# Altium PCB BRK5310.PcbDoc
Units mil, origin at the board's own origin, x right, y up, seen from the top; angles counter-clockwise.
Board outline 4724.41 x 3149.61 mil, 2 copper layers (Top Layer, Bottom Layer), stack 64.8 mil thick; 32 components, 137 nets, 370 pads, 84 vias.
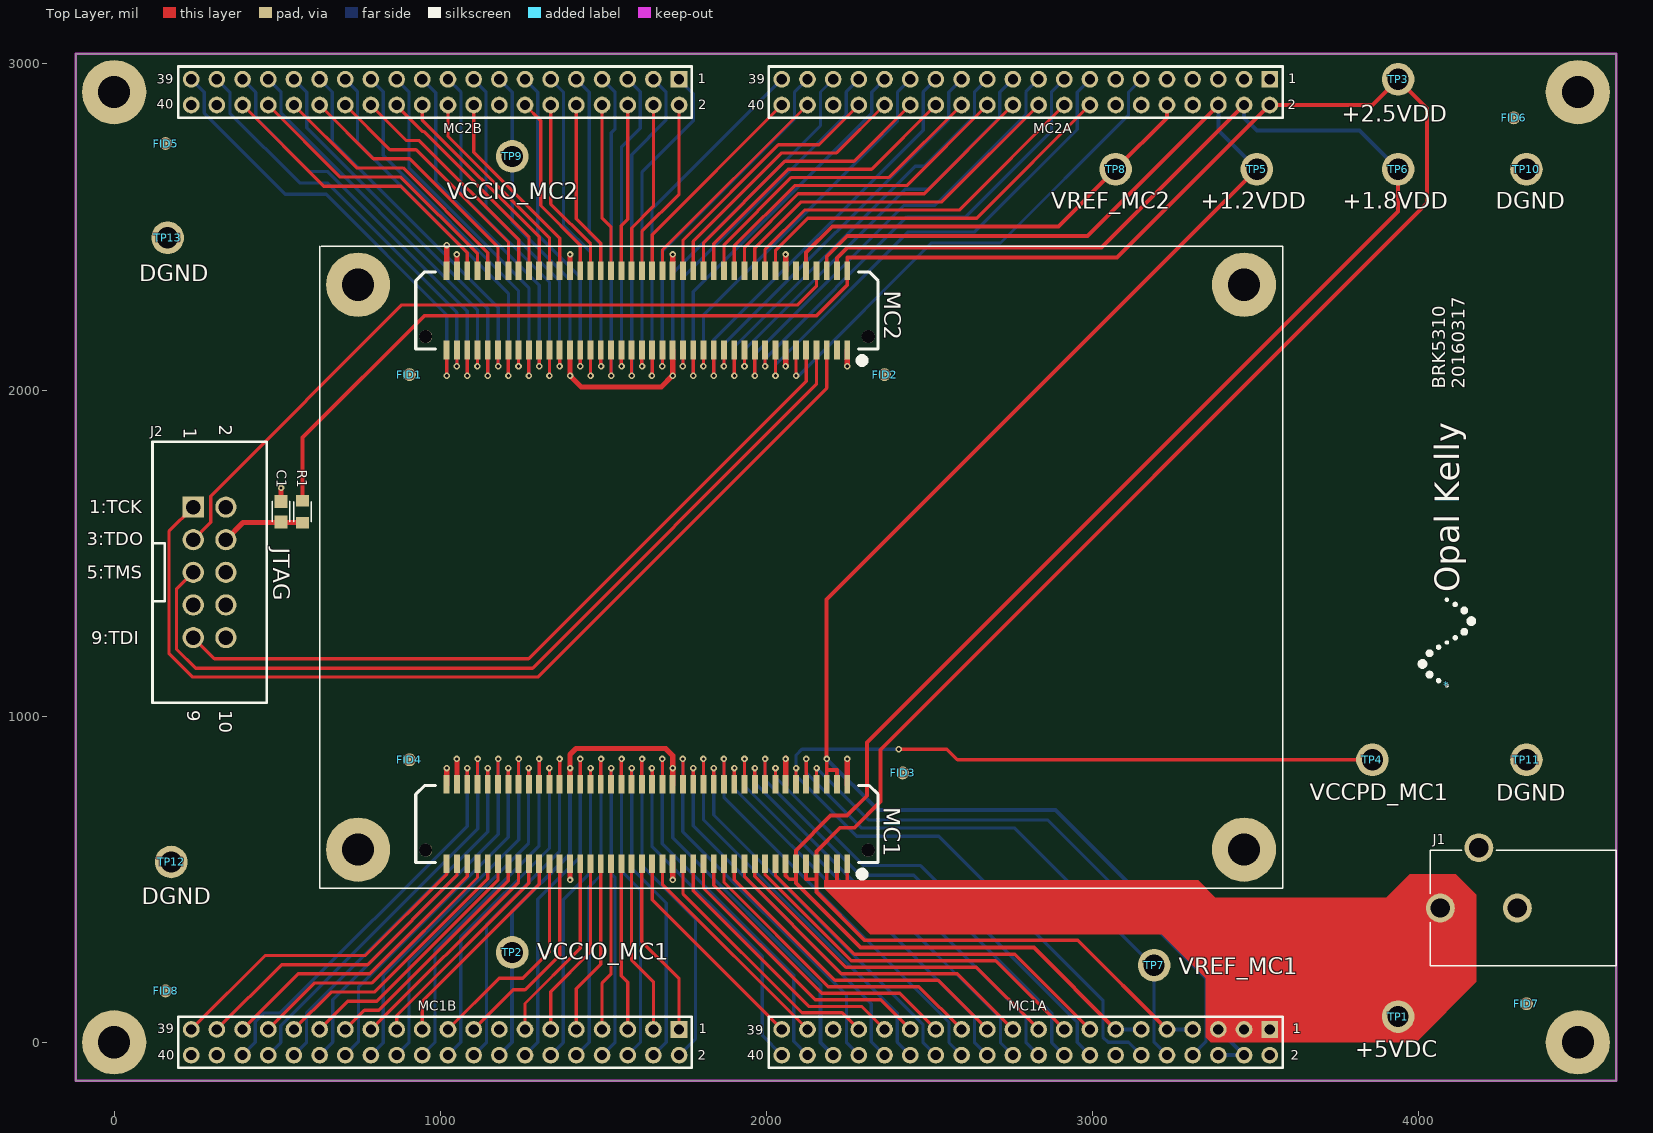
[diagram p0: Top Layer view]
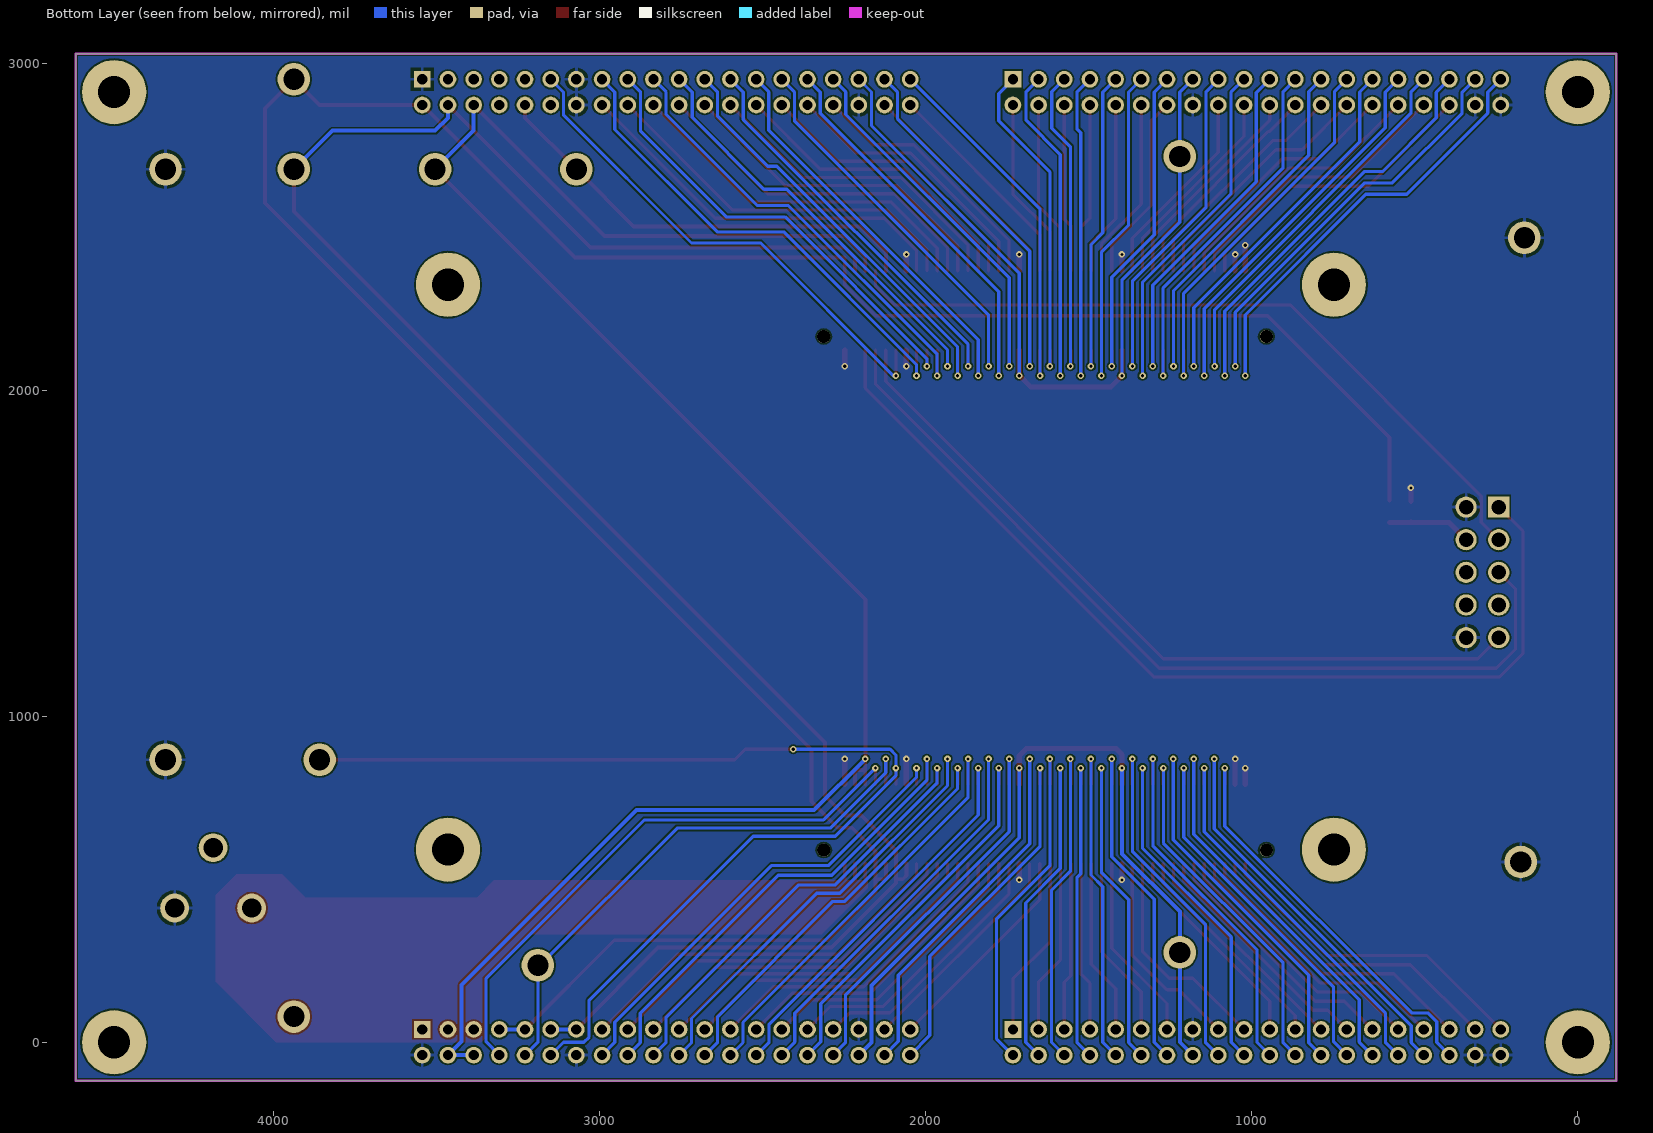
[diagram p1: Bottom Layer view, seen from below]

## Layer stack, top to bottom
Top Solder: solder mask 0.4, Solder Resist, Dk 3.5
Top Layer: signal copper 1.4
Dielectric1: core 62, FR-4, Dk 4.8
Bottom Layer: signal copper 1.4
Bottom Solder: solder mask 0.4, Solder Resist, Dk 3.5

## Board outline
-118.11,-118.11 -118.11,3031.5 4606.3,3031.5 4606.3,-118.11

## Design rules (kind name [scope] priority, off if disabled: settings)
Clearance [All] p1: gap=5
FabricationTestPointUsage TestPointUsage [All] p1: valid=0 allowmultiple=FALSE
FabricationTestpoint Testpoint [All] p1: side=3 testpointundercomponent=TRUE minsize=40 maxsize=100 preferedsize=60 minholesize=0 maxholesize=40 preferedholesize=32 testpointgrid=1 allowsidetop=TRUE allowsidebottom=TRUE usegrid=TRUE gridtolerance=0.01
HoleSize [All] p1: absolutevalues=TRUE maxlimit=236.22 minlimit=10 maxpercent=80.000 minpercent=20.000
MinimumSolderMaskSliver [All] p1: minsoldermaskwidth=3
PolygonConnect "Via Connect" [IsVia] p1: connectstyle=Direct reliefconductorwidth=10 reliefentries=4 polygonreliefangle="90 Angle" airgapwidth=10
PolygonConnect [All] p2: connectstyle=Relief reliefconductorwidth=10 reliefentries=4 polygonreliefangle="90 Angle" airgapwidth=10
RoutingVias [All] p1: holewidth=15 width=25 viastyle="Through Hole" minholewidth=10 minwidth=20 maxholewidth=50 maxwidth=100
SilkToSilkClearance [All] p1: silktosilkclearance=0.1
SilkToSolderMaskClearance SilkscreenOverComponentPads [IsPad] p1: minsilkscreentomaskgap=3 clearancetoexposedcopper=TRUE
SolderMaskExpansion [All] p1: expansion=4
Width okWidthPower [InNetClass('Power')] p1: maxlimit=100 minlimit=10 preferedwidth=10 minimp=50.000000 maximp=50.000000 favimp=50.000000
Width [All] p2: maxlimit=40 minlimit=6 preferedwidth=7 minimp=50.000000 maximp=50.000000 favimp=50.000000
24 further rules are at their usual default settings.

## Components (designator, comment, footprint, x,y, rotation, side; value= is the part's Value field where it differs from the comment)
* "Opal Kelly Logo" okLogo-23x5 4086.61,1094.49 r90 top
C1 "C0603C104K4RACTU" CAPC1608N 511.89,1626.89 r270 top
FID1 "FIDUCIAL" FID1MM/2MM-SS 905.51,2047.24 r90 top
FID2 "FIDUCIAL" FID1MM/2MM-SS 2362.21,2047.24 r90 top
FID3 "FIDUCIAL" FID1MM/2MM-SS 2417.89,825.89 r90 top
FID4 "FIDUCIAL" FID1MM/2MM-SS 905.51,866.14 r90 top
FID5 "FIDUCIAL" FID1MM/2MM-SS 157.48,2755.91 r90 top
FID6 "FIDUCIAL" FID1MM/2MM-SS 4291.34,2834.65 r90 top
FID7 "FIDUCIAL" FID1MM/2MM-SS 4330.71,118.11 r90 top
FID8 "FIDUCIAL" FID1MM/2MM-SS 157.48,157.48 r90 top
J1 "PJ-102AH" CUI-PJ102A 4605.83,411.5 r90 top
J2 "JTAG" HDR2X5-SHRD 292.52,1440.94 r270 top
MC1 "BTE-040-01-F-D-A" BTE-040 1633.86,669.29 r180 top locked
MC1A "0877584016" HDR2X20-2MM 2795.28,0 r180 top locked
MC1B "0877584016" HDR2X20-2MM 984.25,0 r180 top locked
MC2 "BTE-040-01-F-D-A" BTE-040 1633.86,2244.09 r180 top locked
MC2A "0877584016" HDR2X20-2MM 2795.28,2913.39 r180 top locked
MC2B "0877584016" HDR2X20-2MM 984.25,2913.39 r180 top locked
R1 "CRCW06030000Z0EA" RESC1608N 577.89,1626.89 r90 top
TP1 "+5VDC" TP_MED 3937.01,78.74 r0 top
TP2 "VCCIO_MC1" TP_MED 1220.47,275.59 r0 top
TP3 "+2.5VDD" TP_MED 3937.01,2952.76 r0 top
TP4 "VCCPD_MC1" TP_MED 3858.27,866.14 r0 top
TP5 "+1.2VDD" TP_MED 3503.94,2677.17 r0 top
TP6 "+1.8VDD" TP_MED 3937.01,2677.17 r0 top
TP7 "VREF_MC1" TP_MED 3188.98,236.22 r0 top
TP8 "VREF_MC2" TP_MED 3070.87,2677.17 r0 top
TP9 "VCCIO_MC2" TP_MED 1220.47,2716.54 r0 top
TP10 "DGND" TP_MED 4330.71,2677.17 r90 top
TP11 "DGND" TP_MED 4330.71,866.14 r90 top
TP12 "DGND" TP_MED 174.89,552.89 r90 top
TP13 "DGND" TP_MED 163.89,2466.89 r90 top

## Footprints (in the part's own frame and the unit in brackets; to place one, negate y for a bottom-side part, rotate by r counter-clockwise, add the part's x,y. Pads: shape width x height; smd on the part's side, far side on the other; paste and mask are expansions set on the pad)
BTE-040 [mm] "0.8mm Samtech socket"
  rect 0.46x1.45 smd: 1(-15.6,3.085) 2(-15.6,-3.085) 3(-14.8,3.085) 4(-14.8,-3.085) 5(-14,3.085) 6(-14,-3.085) 7(-13.2,3.085) 8(-13.2,-3.085) 9(-12.4,3.085) 10(-12.4,-3.085) 11(-11.6,3.085) 12(-11.6,-3.085) 13(-10.8,3.085) 14(-10.8,-3.085) 15(-10,3.085) 16(-10,-3.085) 17(-9.2,3.085) 18(-9.2,-3.085) 19(-8.4,3.085) 20(-8.4,-3.085) 21(-7.6,3.085) 22(-7.6,-3.085) 23(-6.8,3.085) 24(-6.8,-3.085) 25(-6,3.085) 26(-6,-3.085) 27(-5.2,3.085) 28(-5.2,-3.085) 29(-4.4,3.085) 30(-4.4,-3.085) 31(-3.6,3.085) 32(-3.6,-3.085) 33(-2.8,3.085) 34(-2.8,-3.085) 35(-2,3.085) 36(-2,-3.085) 37(-1.2,3.085) 38(-1.2,-3.085) 39(-0.4,3.085) 40(-0.4,-3.085) 41(0.4,3.085) 42(0.4,-3.085) 43(1.2,3.085) 44(1.2,-3.085) 45(2,3.085) 46(2,-3.085) 47(2.8,3.085) 48(2.8,-3.085) 49(3.6,3.085) 50(3.6,-3.085) 51(4.4,3.085) 52(4.4,-3.085) 53(5.2,3.085) 54(5.2,-3.085) 55(6,3.085) 56(6,-3.085) 57(6.8,3.085) 58(6.8,-3.085) 59(7.6,3.085) 60(7.6,-3.085) 61(8.4,3.085) 62(8.4,-3.085) 63(9.2,3.085) 64(9.2,-3.085) 65(10,3.085) 66(10,-3.085) 67(10.8,3.085) 68(10.8,-3.085) 69(11.6,3.085) 70(11.6,-3.085) 71(12.4,3.085) 72(12.4,-3.085) 73(13.2,3.085) 74(13.2,-3.085) 75(14,3.085) 76(14,-3.085) 77(14.8,3.085) 78(14.8,-3.085) 79(15.6,3.085) 80(15.6,-3.085)
  round 1.02 hole 1.02: 81(-17.235,2.035) 82(17.235,2.035)
  silkscreen extent -18,-3 18,4.15
CAPC1608N [mm] "Chip Capacitor, Body 1.6x0.8mm, IPC Medium Density"
  rect 1x1 smd: 1(-0.8,0) 2(0.8,0)
  silkscreen extent -0.8,-0.68 0.8,0.68, body extent -0.87,-0.48 0.87,0.48, height 0.85
CUI-PJ102A [mm] "2.1mm/5.5mm DC power jack"
  round 2.25 hole 1.5: 1(0,13.7) 2(0,7.7) 3(4.7,10.7)
  silkscreen extent -4.5,0 4.5,14.5
FID1MM/2MM-SS [mm] "Fiducial 1mm copper, 2mm soldermask, single-side"
  round 1 smd paste-0.5 mask+0.5: FID?(0,0)
HDR2X5-SHRD [mil] "0.1\" 2x5 shrouded header"
  rect 65x65 hole 44.88: 1(-200,-50)
  round 65 hole 44.88: 2(-200,50) 3(-100,-50) 4(-100,50) 5(0,-50) 6(0,50) 7(100,-50) 8(100,50) 9(200,-50) 10(200,50)
  silkscreen extent -400,-175 400,175
HDR2X20-2MM [mm] "2mm 2x20 header"
  rect 1.3x1.3 hole 0.8: 1(-19,-1)
  round 1.3 hole 0.8: 2(-19,1) 3(-17,-1) 4(-17,1) 5(-15,-1) 6(-15,1) 7(-13,-1) 8(-13,1) 9(-11,-1) 10(-11,1) 11(-9,-1) 12(-9,1) 13(-7,-1) 14(-7,1) 15(-5,-1) 16(-5,1) 17(-3,-1) 18(-3,1) 19(-1,-1) 20(-1,1) 21(1,-1) 22(1,1) 23(3,-1) 24(3,1) 25(5,-1) 26(5,1) 27(7,-1) 28(7,1) 29(9,-1) 30(9,1) 31(11,-1) 32(11,1) 33(13,-1) 34(13,1) 35(15,-1) 36(15,1) 37(17,-1) 38(17,1) 39(19,-1) 40(19,1)
  silkscreen extent -20,-2 20,2
okLogo-23x5 [mil] "Opal Kelly silkscreen logo (23mm x 5mm)"
  silkscreen extent -3,-82 266,82
RESC1608N [mm] "Chip Resistor, Body 1.6x0.8mm, IPC Medium Density"
  rect 0.9x1 smd: 1(-0.85,0) 2(0.85,0)
  silkscreen extent -0.77,-0.68 0.78,0.68, body extent -0.85,-0.48 0.85,0.48, height 0.6
TP_MED [mil] "Testpoint - medium sized"
  round 100 hole 65: 1(0,0)

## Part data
*: library part OKLOGO
C1: library part 000019, "Ceramic capacitor"
FID1 FID2 FID3 FID4 FID5 FID6 FID7 FID8: "PCB fiducial"
J1: library part 000356, "DC power connector - high current"
J2: library part 000777, "2.54mm, 10 Pos, Dual Row Header"
MC1 MC2: library part 000059, "0.8mm high-density header"
MC1A MC1B MC2A MC2B: library part 000583, "2mm header, 20x2, thru-hole"
R1: library part 000411, "Zero-ohm resistor"
TP1 TP2 TP3 TP4 TP5 TP6 TP7 TP8 TP9 TP10 TP11 TP12 TP13: library part 000265, "Testpoint"

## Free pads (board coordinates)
  round 196.85 hole 98.43: 0(0,0) 0(0,2913.39) 0(4488.19,0) 0(4488.19,2913.39) MH(748.03,590.55) MH(748.03,2322.83) MH(3464.57,590.55) MH(3464.57,2322.83)

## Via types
v1: diameter 20, hole 10, Top Layer to Bottom Layer, 84 vias

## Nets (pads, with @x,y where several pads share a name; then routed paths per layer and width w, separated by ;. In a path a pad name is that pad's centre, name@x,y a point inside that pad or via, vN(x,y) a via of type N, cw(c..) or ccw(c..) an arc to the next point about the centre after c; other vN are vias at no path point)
+1.2VDD: MC1.4 MC1.6 MC1A.4 MC1A.6 MC2.6 MC2A.6 TP5.1 | length 6028
  Top Layer w12: MC1.6 2185.04,834.89 ; MC2.6 2185.04,2410.04 2247.89,2472.89 2984.7,2472.89 MC2A.6 ; MC1.4 2216.54,834.89 2185.04,834.89 ; TP5.1 2184.89,1358.12 v1(2184.89,868.89) 2185.04,868.74 2185.04,834.89
  Bottom Layer w12: v1(2184.89,868.89) 2341.89,711.89 2886.89,711.89 3423.42,175.36 3423.42,1.78 MC1A.4 MC1A.6 ; MC2A.6 3385.83,2795.27 TP5.1
+1.8VDD: MC1.11 MC1.13 MC1A.11 MC1A.13 MC2.4 MC2A.4 TP6.1 | length 6359.5
  Top Layer w12: MC1.13 2059.05,510.95 2070,500 2090.55,500 ; MC2.4 2216.54,2404.53 2248.89,2436.89 3027.44,2436.89 MC2A.4 ; MC1A.13@3070.87,39.37 2820.24,290 2288.78,290 2090.55,488.23 2090.55,500 ; TP6.1 3937.01,2548.01 2307.89,918.89 2307.89,755.89 2246.89,694.89 2196.89,694.89 2090.55,588.55 MC1.11 2090.55,500
  Bottom Layer w12: MC1A.13@3070.87,39.37 MC1A.11 ; MC2A.4 3464.57,2834.64 3503.94,2795.28 3818.9,2795.28 TP6.1
+2.5VDD: MC1.7 MC1.9 MC1A.7 MC1A.9 MC2.2 MC2A.2 R1.2 TP3.1 | length 8794.9
  Top Layer w12: R1.2 577.89,1853.89 951.89,2227.89 2153.89,2227.89 2248.03,2322.03 MC2.2 2248.03,2405.89 3075.18,2405.89 MC2A.2 3858.27,2874.02 TP3.1 4025.89,2863.87 4025.89,2572.89 2349.89,896.89 2349.89,737.89 2269.89,657.89 2225.89,657.89 2153.54,585.54 MC1.7 2153.54,499.89 ; MC1.9 2122.05,499.89 2153.54,499.89 ; MC1A.9 2954.83,312.89 2300.89,312.89 2153.54,460.24 2153.54,499.89
  Bottom Layer w12: MC1A.9 MC1A.7
+5VDC: J1.1 MC1.1 MC1.3 MC1.5 MC1A.1 MC1A.3 MC1A.5 TP1.1 | length 266.8
  Top Layer w12: MC1.5 2185.04,479.89 2216.54,479.89 ; MC1.3 2216.54,479.89 ; MC1.1 2248.03,479.89 2216.54,479.89
B2A_RX_L10N: MC1.17 MC1A.17 | length 1147.8
  Top Layer w10: MC1.17 1996.06,513.94 2260,250 2702.76,250 MC1A.17
B2A_RX_L10P: MC1.15 MC1A.15 | length 1195.9
  Top Layer w10: MC1.15 2027.56,512.44 2270,270 2761.5,270 MC1A.15
B2A_RX_L11N: MC1.21 MC1A.21 | length 1057.4
  Top Layer w10: MC1.21 1933.07,506.93 2230,210 2585.28,210 MC1A.21
B2A_RX_L11P: MC1.19 MC1A.19 | length 1103.3
  Top Layer w10: MC1.19 1964.57,509.21 2243.89,229.89 2644.13,229.89 MC1A.19
B2A_RX_L14N: MC1.29 MC1A.29 | length 888.4
  Top Layer w10: MC1.29 1807.09,472.91 2150,130 2350.32,130 MC1A.29
B2A_RX_L14P: MC1.27 MC1A.27 | length 930.6
  Top Layer w10: MC1.27 1838.58,481.42 2170,150 2409.06,150 MC1A.27
B2A_RX_L15N: MC1.25 MC1A.25 | length 972.9
  Top Layer w10: MC1.25 1870.08,489.92 2190,170 2467.8,170 MC1A.25
B2A_RX_L15P: MC1.23 MC1A.23 | length 1015.1
  Top Layer w10: MC1.23 1901.57,498.43 2210,190 2526.54,190 MC1A.23
B2A_TX_L9N: MC1.30 MC1A.30 | length 1249.2
  Top Layer w10: v1(1806.89,868.89) 1807.09,868.89 MC1.30
  Bottom Layer w10: v1(1806.89,868.89) 1806.89,683.11 2400.89,89.11 2400.89,0.69 MC1A.30
B2A_TX_L9P: MC1.28 MC1A.28 | length 1212.7
  Top Layer w10: MC1.28 1838.58,840.89 v1(1838.89,840.89)
  Bottom Layer w10: v1(1838.89,840.89) 1838.89,696.89 2479.89,55.89 2479.89,0.43 MC1A.28
B2A_TX_L12N: MC1.22 MC1A.22 | length 1368.9
  Top Layer w10: v1(1932.89,868.89) 1933.07,868.89 MC1.22
  Bottom Layer w10: v1(1932.89,868.89) 1932.89,787.11 2263.11,456.89 2333.89,456.89 2717.89,72.89 2717.89,-1.35 MC1A.22
B2A_TX_L12P: MC1.20 MC1A.20 | length 1357.1
  Top Layer w10: MC1.20 1964.57,840.89 v1(1964.89,840.89)
  Bottom Layer w10: v1(1964.89,840.89) 1964.89,795.11 2278.11,481.89 2390.89,481.89 2795.89,76.89 2795.89,-0.61 MC1A.20
B2A_TX_L13N: MC1.26 MC1A.26 | length 1288.4
  Top Layer w10: v1(1869.89,868.89) 1870.08,868.89 MC1.26
  Bottom Layer w10: v1(1869.89,868.89) 1869.89,750.89 2560,60.78 2560,-0.94 MC1A.26
B2A_TX_L13P: MC1.24 MC1A.24 | length 1273.4
  Top Layer w10: MC1.24 1901.57,840.89 v1(1901.89,840.89)
  Bottom Layer w10: v1(1901.89,840.89) 1901.89,778.11 2248.11,431.89 2284.89,431.89 2637.89,78.89 2637.89,-0.09 MC1A.24
B2A_TX_L16N: MC1.18 MC1A.18 | length 1462.6
  Top Layer w10: v1(1995.89,868.89) 1996.06,868.89 MC1.18
  Bottom Layer w10: v1(1995.89,868.89) 1995.89,804.11 2288.11,511.89 2451.89,511.89 2874.89,88.89 2874.89,-0.87 MC1A.18
B2A_TX_L16P: MC1.16 MC1A.16 | length 1432.5
  Top Layer w10: MC1.16 2027.56,840.89 v1(2027.89,840.89)
  Bottom Layer w10: v1(2027.89,840.89) 2027.89,812.11 2298.11,541.89 2472.89,541.89 2952.89,61.89 2952.89,-0.13 MC1A.16
B4A_CLK2N: MC2.79 MC2B.39 | length 1385.4
  Top Layer w10: v1@1019.68,2043.89 MC2.79
  Bottom Layer w10: MC2B.39 275.89,2913.09 275.89,2849.11 525,2600 650,2600 1019.89,2230.11 v1(1019.89,2043.89)
B4A_CLK2P: MC2.77 MC2B.37 | length 1284.2
  Top Layer w10: v1@1051.18,2072.89 MC2.77
  Bottom Layer w10: MC2B.37 354.89,2912.83 354.89,2848.89 568.78,2635 653.78,2635 1050.89,2237.89 v1(1050.89,2072.89)
B4A_RX_B26N: MC2.17 MC2A.17 | length 1415.2
  Top Layer w10: v1(1995.89,2072.89) 1996.06,2073.06 MC2.17
  Bottom Layer w10: v1(1995.89,2072.89) 1995.89,2095.89 2430.89,2530.89 2610.89,2530.89 2873.89,2793.89 2873.89,2913.26 MC2A.17
B4A_RX_B26P: MC2.15 MC2A.15 | length 1506.7
  Top Layer w10: MC2.15 2027.56,2044.22 v1(2027.89,2043.89)
  Bottom Layer w10: v1(2027.89,2043.89) 2027.89,2077.89 2434.89,2484.89 2638.89,2484.89 2952.9,2798.9 2952.9,2913.53 MC2A.15
B4A_RX_B27N: MC2.21 MC2A.21 | length 1311.6
  Top Layer w10: v1(1932.89,2072.89) 1933.07,2073.07 MC2.21
  Bottom Layer w10: v1(1932.89,2072.89) 1932.89,2122.89 2425.89,2615.89 2495.89,2615.89 2715.89,2835.89 2715.89,2912.74 MC2A.21
B4A_RX_B27P: MC2.19 MC2A.19 | length 1404.2
  Top Layer w10: MC2.19 1964.57,2044.21 v1(1964.89,2043.89)
  Bottom Layer w10: v1(1964.89,2043.89) 1964.89,2109.89 2420.89,2565.89 2516.89,2565.89 2795.89,2844.89 2795.89,2914 MC2A.19
B4A_RX_B30N: MC2.25 MC2A.25 | length 1231.5
  Top Layer w10: v1(1869.89,2072.89) 1870.08,2073.08 MC2.25
  Bottom Layer w10: v1(1869.89,2072.89) 1869.89,2139.89 2559.3,2829.3 2559.3,2913.63 MC2A.25
B4A_RX_B30P: MC2.23 MC2A.23 | length 1325.3
  Top Layer w10: MC2.23 1901.57,2044.21 v1(1901.89,2043.89)
  Bottom Layer w10: v1(1901.89,2043.89) 1901.89,2131.89 2455.89,2685.89 2483.89,2685.89 2637.89,2839.89 2637.89,2913.48 MC2A.23
B4A_RX_B34N: MC2.29 MC2A.29 | length 1192.3
  Top Layer w10: v1(1806.89,2072.89) 1807.09,2073.09 MC2.29
  Bottom Layer w10: v1(1806.89,2072.89) 1806.89,2229.89 2402.14,2825.14 2402.14,2913.95 MC2A.29
B4A_RX_B34P: MC2.27 MC2A.27 | length 1269.7
  Top Layer w10: MC2.27 1838.58,2044.2 v1(1838.89,2043.89)
  Bottom Layer w10: v1(1838.89,2043.89) 1838.89,2153.89 2480.89,2795.89 2480.89,2913.96 MC2A.27
B4A_RX_B35N: MC2.33 MC2A.33 | length 1153.2
  Top Layer w10: v1(1743.89,2072.89) 1744.09,2073.09 MC2.33
  Bottom Layer w10: v1(1743.89,2072.89) 1743.89,2343.89 2244.89,2844.89 2244.89,2914.18 MC2A.33
B4A_RX_B35P: MC2.31 MC2A.31 | length 1230.6
  Top Layer w10: MC2.31 1775.59,2044.19 v1(1775.89,2043.89)
  Bottom Layer w10: v1(1775.89,2043.89) 1775.89,2301.46 2322.89,2848.46 2322.89,2913.44 MC2A.31
B4A_RX_B38N: MC2.39 MC2A.39 | length 1152.9
  Top Layer w10: v1(1648.89,2043.89) 1649.61,2044.61 MC2.39
  Bottom Layer w10: v1(1648.89,2043.89) 1648.89,2554.4 MC2A.39
B4A_RX_B38P: MC2.37 MC2A.37 | length 1114.1
  Top Layer w10: v1(1680.89,2072.89) 1681.1,2073.1 MC2.37
  Bottom Layer w10: v1(1680.89,2072.89) 1680.89,2425.89 2085.89,2830.89 2085.89,2912.66 MC2A.37
B4A_RX_B39N: MC2.43 MC2B.3 | length 1047.1
  Top Layer w10: MC2.43 1586.61,2044.17 v1(1586.89,2043.89)
  Bottom Layer w10: v1(1586.89,2043.89) 1586.89,2721.89 1691.89,2826.89 1691.89,2914.41 MC2B.3
B4A_RX_B39P: MC2.41 MC2B.1 | length 1013
  Top Layer w10: MC2.41 1618.11,2073.67 v1(1618.89,2072.89)
  Bottom Layer w10: v1(1618.89,2072.89) 1618.89,2668.89 1775.89,2825.89 1775.89,2909.15 MC2B.1
B4A_RX_B42N: MC2.47 MC2B.7 | length 1009.2
  Top Layer w10: MC2.47 1523.62,2044.16 v1(1523.89,2043.89)
  Bottom Layer w10: MC2B.7 1535.89,2912.93 1535.89,2800.89 1523.89,2788.89 v1(1523.89,2043.89)
B4A_RX_B42P: MC2.45 MC2B.5 | length 969.3
  Top Layer w10: MC2.45 1555.12,2073.66 v1(1555.89,2072.89)
  Bottom Layer w10: v1(1555.89,2072.89) 1555.89,2745.89 1612.89,2802.89 1612.89,2914.67 MC2B.5
B4A_RX_B43N: MC2.51 MC2B.11 | length 1038.4
  Top Layer w10: MC2.51 1460.63,2044.15 v1(1460.89,2043.89)
  Bottom Layer w10: MC2B.11 1377.89,2913.45 1377.89,2504.89 1460.89,2421.89 v1(1460.89,2043.89)
B4A_RX_B43P: MC2.49 MC2B.9 | length 961.2
  Top Layer w10: MC2.49 1492.13,2073.65 v1(1492.89,2072.89)
  Bottom Layer w10: MC2B.9 1456.89,2913.19 1456.89,2481.89 1492.89,2445.89 v1(1492.89,2072.89)
B4A_RX_B46N: MC2.57 MC2B.17 | length 1038.9
  Top Layer w10: v1(1365.89,2072.89) 1366.14,2073.14 MC2.57
  Bottom Layer w10: MC2B.17 1139.89,2915.23 1139.89,2560.11 1365.89,2334.11 v1(1365.89,2072.89)
B4A_RX_B46P: MC2.53 MC2B.13 | length 999.7
  Top Layer w10: v1(1428.89,2072.89) 1429.13,2073.13 MC2.53
  Bottom Layer w10: MC2B.13 1298.89,2913.71 1298.89,2476.11 1428.89,2346.11 v1(1428.89,2072.89)
B4A_RX_B47N: MC2.61 MC2B.21 | length 1078.6
  Top Layer w10: MC2.61 1303.15,2073.63 v1(1303.89,2072.89)
  Bottom Layer w10: MC2B.21 985.89,2911.75 985.89,2639.11 1303.89,2321.11 v1(1303.89,2072.89)
B4A_RX_B47P: MC2.59 MC2B.19 | length 1116.6
  Top Layer w10: MC2.59 1334.65,2044.13 v1(1334.89,2043.89)
  Bottom Layer w10: MC2B.19 1063.89,2912.49 1063.89,2601.11 1334.89,2330.11 v1(1334.89,2043.89)
B4A_TX_B25N: MC2.18 MC2A.18 | length 1166.3
  Top Layer w10: MC2.18 1996.06,2431.06 2116.89,2551.89 2591.26,2551.89 MC2A.18
B4A_TX_B25P: MC2.16 MC2A.16 | length 1211.5
  Top Layer w10: MC2.16 2027.56,2427.56 2126.89,2526.89 2645,2526.89 MC2A.16
B4A_TX_B28N: MC2.22 MC2A.22 | length 1075.9
  Top Layer w10: MC2.22 1933.07,2438.07 2096.89,2601.89 2483.78,2601.89 MC2A.22
B4A_TX_B28P: MC2.20 MC2A.20 | length 1121.1
  Top Layer w10: MC2.20 1964.57,2434.57 2106.89,2576.89 2537.52,2576.89 MC2A.20
B4A_TX_B29N: MC2.26 MC2A.26 | length 985.3
  Top Layer w10: MC2.26@1870.28,2365.75 1870.28,2445.28 2076.89,2651.89 2376.3,2651.89 MC2A.26
B4A_TX_B29P: MC2.24 MC2A.24 | length 1030.5
  Top Layer w10: MC2.24@1901.77,2365.75 1901.77,2441.77 2086.89,2626.89 2430.04,2626.89 MC2A.24
B4A_TX_B32N: MC2.30 MC2A.30 | length 894.9
  Top Layer w10: MC2.30@1807.28,2365.75 1807.28,2452.28 2056.89,2701.89 2268.82,2701.89 MC2A.30
B4A_TX_B32P: MC2.28 MC2A.28 | length 940.1
  Top Layer w10: MC2.28@1838.78,2365.75 1838.78,2448.78 2066.89,2676.89 2322.56,2676.89 MC2A.28
B4A_TX_B33N: MC2.34 MC2A.34 | length 804.5
  Top Layer w10: MC2.34@1744.29,2365.75 1744.29,2459.29 2036.89,2751.89 2161.34,2751.89 MC2A.34
B4A_TX_B33P: MC2.32 MC2A.32 | length 849.7
  Top Layer w10: MC2.32@1775.79,2365.75 1775.79,2455.79 2046.89,2726.89 2215.08,2726.89 MC2A.32
B4A_TX_B36N: MC2.40 MC2A.40 | length 672.9
  Top Layer w10: MC2.40@1649.8,2365.75 1649.8,2476.58 MC2A.40
B4A_TX_B36P: MC2.38 MC2A.38 | length 692.5
  Top Layer w10: MC2.38@1681.3,2365.75 1681.3,2429.33 MC2A.38
B4A_TX_B37N: MC2.44 MC2B.4 | length 535.9
  Top Layer w10: MC2.44@1586.81,2365.75 1586.81,2496.81 1653.54,2563.54 MC2B.4
B4A_TX_B37P: MC2.42 MC2B.2 | length 555.5
  Top Layer w10: MC2.42@1618.31,2365.75 1618.31,2486.31 1732.28,2600.28 MC2B.2
B4A_TX_B40N: MC2.48 MC2B.8 | length 519.8
  Top Layer w10: MC2B.8 1496.06,2526.72 1523.82,2498.96 MC2.48@1523.82,2365.75
B4A_TX_B40P: MC2.46 MC2B.6 | length 516.3
  Top Layer w10: MC2.46@1555.32,2365.75 1555.32,2504.31 1574.8,2523.8 MC2B.6
B4A_TX_B41N: MC2.52 MC2B.12 | length 558.9
  Top Layer w10: MC2B.12 1338.58,2570.2 1460.83,2447.95 MC2.52@1460.83,2365.75
B4A_TX_B41P: MC2.50 MC2B.10 | length 539.3
  Top Layer w10: MC2B.10 1417.32,2525.46 1492.32,2450.46 MC2.50@1492.32,2365.75
B4A_TX_B44N: MC2.58 MC2B.18 | length 617.6
  Top Layer w10: MC2B.18 1102.36,2729.42 1366.34,2465.44 MC2.58@1366.34,2365.75
B4A_TX_B44P: MC2.54 MC2B.14 | length 578.5
  Top Layer w10: MC2B.14 1307.89,2825.97 1307.89,2565.89 1429.33,2444.45 MC2.54@1429.33,2365.75
B4A_TX_B45N: MC2.62 MC2B.22 | length 656.7
  Top Layer w10: MC2B.22 944.88,2827.9 1303.35,2469.43 MC2.62@1303.35,2365.75
B4A_TX_B45P: MC2.60 MC2B.20 | length 637.2
  Top Layer w10: MC2B.20 1023.62,2778.16 1334.84,2466.94 MC2.60@1334.84,2365.75
B4A_TX_B48N: MC2.66 MC2B.26 | length 718.9
  Top Layer w10: MC2B.26 896.42,2765 935.78,2765 1240.35,2460.43 MC2.66@1240.35,2365.75
B4A_TX_B48P: MC2.64 MC2B.24 | length 678.5
  Top Layer w10: MC2B.24 866.14,2871.86 945,2793 948.78,2793 1271.85,2469.93 MC2.64@1271.85,2365.75
B5A_RX_R2N: MC1.39 MC1A.39 | length 673.2
  Top Layer w10: MC1.39 1649.61,437.01 MC1A.39
B5A_RX_R2P: MC1.37 MC1A.37 | length 692.7
  Top Layer w10: MC1.37 1681.1,484.25 MC1A.37
B5A_RX_R4N: MC1.43 MC1B.3 | length 536.2
  Top Layer w10: MC1.43 1586.61,252.17 1653.54,185.24 MC1B.3
B5A_RX_R4P: MC1.41 MC1B.1 | length 555.8
  Top Layer w10: MC1.41 1618.11,308.67 1732.28,194.5 MC1B.1
B5A_RX_R6N: MC1.47 MC1B.7 | length 519.9
  Top Layer w10: MC1B.7 1496.06,182.06 1523.62,209.62 MC1.47
B5A_RX_R6P: MC1.45 MC1B.5 | length 516.6
  Top Layer w10: MC1.45 1555.12,203.66 1574.8,183.98 MC1B.5
B5A_RX_R8N: MC1.33 MC1A.33 | length 803.8
  Top Layer w10: MC1.33 1744.09,455.91 2109.11,90.89 2231.94,90.89 MC1A.33
B5A_RX_R8P: MC1.31 MC1A.31 | length 846.1
  Top Layer w10: MC1.31 1775.59,464.41 2130,110 2291.58,110 MC1A.31
B5A_TX_R1N: MC1.40 MC1A.40 | length 1096.1
  Top Layer w10: v1(1648.89,840.89) 1649.61,840.89 MC1.40
  Bottom Layer w10: v1(1648.89,840.89) 1648.89,601.11 1986.89,263.11 1986.89,20.98 MC1A.40
B5A_TX_R1P: MC1.38 MC1A.38 | length 1171
  Top Layer w10: v1(1680.89,868.89) 1681.1,868.89 MC1.38
  Bottom Layer w10: v1(1680.89,868.89) 1680.89,609.11 2083.89,206.11 2083.89,2.72 MC1A.38
B5A_TX_R3N: MC1.44 MC1B.4 | length 990.9
  Top Layer w10: MC1.44 1586.61,840.89 v1(1586.89,840.89)
  Bottom Layer w10: v1(1586.89,840.89) 1586.89,533.11 1692.89,427.11 1692.89,-0.02 MC1B.4
B5A_TX_R3P: MC1.42 MC1B.2 | length 1076.1
  Top Layer w10: MC1.42 1618.11,868.89 v1(1618.89,868.89)
  Bottom Layer w10: v1(1618.89,868.89) 1618.89,541.11 1782.89,377.11 1782.89,11.24 MC1B.2
B5A_TX_R5N: MC1.48 MC1B.8 | length 952.1
  Top Layer w10: MC1.48 1523.62,840.89 v1(1523.89,840.89)
  Bottom Layer w10: MC1B.8 1535.89,0.46 1535.89,504.11 1523.89,516.11 v1(1523.89,840.89)
B5A_TX_R5P: MC1.46 MC1B.6 | length 1027.4
  Top Layer w10: MC1.46 1555.12,868.89 v1(1555.89,868.89)
  Bottom Layer w10: v1(1555.89,868.89) 1555.89,524.11 1613.89,466.11 1613.89,-0.28 MC1B.6
B5A_TX_R7N: MC1.34 MC1A.34 | length 1210.1
  Top Layer w10: v1(1743.89,868.89) 1744.09,868.89 MC1.34
  Bottom Layer w10: v1(1743.89,868.89) 1743.89,646.11 2245.89,144.11 2245.89,-1.8 MC1A.34
B5A_TX_R7P: MC1.32 MC1A.32 | length 1173.6
  Top Layer w10: MC1.32 1775.59,840.89 v1(1775.89,840.89)
  Bottom Layer w10: v1(1775.89,840.89) 1775.89,664.11 2321.89,118.11 2321.89,0.95 MC1A.32
B5B_BR_CLKOUT0: MC1.8 MC1A.8 | length 1763.8
  Top Layer w10: MC1.8 2153.54,840.89 v1(2153.89,840.89)
  Bottom Layer w10: v1(2153.89,840.89) 2312.89,681.89 2861.89,681.89 3347.89,195.89 3347.89,1.43 MC1A.8
B5B_BR_CLKOUT1: MC2.11 MC2A.11 | length 1555.2
  Top Layer w10: MC2.11 2090.55,2044.23 v1(2090.89,2043.89)
  Bottom Layer w10: v1(2090.89,2043.89) 2098.89,2043.89 2505.89,2450.89 2717.89,2450.89 3110.64,2843.64 3110.64,2913.79 MC2A.11
B5B_CLK6N: MC1.79 MC1B.39 | length 1012.9
  Top Layer w10: MC1B.39 462.85,266 770,266 1019.68,515.68 MC1.79
B5B_CLK6P: MC1.77 MC1B.37 | length 967.7
  Top Layer w10: MC1B.37 513.59,238 777,238 1051.18,512.18 MC1.77
B5B_RX_R11N: MC1.51 MC1B.11 | length 559
  Top Layer w10: MC1B.11 1338.58,155.58 1460.63,277.63 MC1.51
B5B_RX_R11P: MC1.49 MC1B.9 | length 539.4
  Top Layer w10: MC1B.9 1417.32,164.32 1492.13,239.13 MC1.49
B5B_RX_R13N: MC1.57 MC1B.17 | length 638.8
  Top Layer w10: MC1B.17 1223.99,161 1260,161 1366.14,267.14 MC1.57
B5B_RX_R13P: MC1.53 MC1B.13 | length 578.6
  Top Layer w10: MC1B.13 1259.84,118.84 1429.13,288.13 MC1.53
B5B_RX_R15N: MC1.61 MC1B.21 | length 656.9
  Top Layer w10: MC1B.21 944.88,125.88 1303.15,484.15 MC1.61
B5B_RX_R15P: MC1.59 MC1B.19 | length 679.9
  Top Layer w10: MC1B.19 1180.25,196 1253,196 1334.65,277.65 MC1.59
B5B_TX_R10N: MC1.52 MC1B.12 | length 981.3
  Top Layer w10: MC1.52 1460.63,840.89 v1(1460.89,840.89)
  Bottom Layer w10: MC1B.12 1376.89,-1.06 1376.89,436.89 1460.89,520.89 v1(1460.89,840.89)
B5B_TX_R10P: MC1.50 MC1B.10 | length 1018.5
  Top Layer w10: MC1.50 1492.13,868.89 v1(1492.89,868.89)
  Bottom Layer w10: MC1B.10 1456.89,0.2 1456.89,476.89 1492.89,512.89 v1(1492.89,868.89)
B5B_TX_R14N: MC1.58 MC1B.18 | length 1095.8
  Top Layer w10: v1(1365.89,868.89) 1366.14,868.89 MC1.58
  Bottom Layer w10: MC1B.18 1141.89,0.16 1141.89,361.89 1365.89,585.89 v1(1365.89,868.89)
B5B_TX_R14P: MC1.54 MC1B.14 | length 1056.7
  Top Layer w10: v1(1428.89,868.89) 1429.13,868.89 MC1.54
  Bottom Layer w10: MC1B.14 1298.89,-0.32 1298.89,438.89 1428.89,568.89 v1(1428.89,868.89)
B5B_TX_R16N: MC1.62 MC1B.22 | length 1135
  Top Layer w10: v1(1302.89,868.89) 1303.15,868.89 MC1.62
  Bottom Layer w10: MC1B.22 983.89,-0.36 983.89,283.89 1302.89,602.89 v1(1302.89,868.89)
B5B_TX_R16P: MC1.60 MC1B.20 | length 1059.6
  Top Layer w10: MC1.60 1334.65,840.89 v1(1334.89,840.89)
  Bottom Layer w10: MC1B.20 1062.89,-0.1 1062.89,322.89 1334.89,594.89 v1(1334.89,840.89)
B7A_RX_T3N: MC2.65 MC2B.25 | length 1117.2
  Top Layer w10: v1(1239.89,2072.89) 1240.16,2073.16 MC2.65
  Bottom Layer w10: MC2B.25 824.89,2915.27 824.89,2720.11 1239.89,2305.11 v1(1239.89,2072.89)
B7A_RX_T3P: MC2.63 MC2B.23 | length 1155.8
  Top Layer w10: MC2.63 1271.65,2044.13 v1(1271.89,2043.89)
  Bottom Layer w10: MC2B.23 903.89,2915.01 903.89,2681.11 1271.89,2313.11 v1(1271.89,2043.89)
B7A_RX_T17N: MC2.69 MC2B.29 | length 1156.9
  Top Layer w10: MC2.69 1177.17,2073.61 v1(1177.89,2072.89)
  Bottom Layer w10: MC2B.29 668.89,2913.79 668.89,2761.11 1177.89,2252.11 v1(1177.89,2072.89)
B7A_RX_T17P: MC2.67 MC2B.27 | length 1194.9
  Top Layer w10: MC2.67 1208.66,2044.12 v1(1208.89,2043.89)
  Bottom Layer w10: MC2B.27 745.89,2915.53 745.89,2759.11 1208.89,2296.11 v1(1208.89,2043.89)
B7A_TX_T2N: MC2.70 MC2B.30 | length 800
  Top Layer w10: MC2B.30 794.94,2709 905.78,2709 1177.36,2437.42 MC2.70@1177.36,2365.75
B7A_TX_T2P: MC2.68 MC2B.28 | length 762.4
  Top Layer w10: MC2B.28 845.68,2737 925.78,2737 1208.86,2453.92 MC2.68@1208.86,2365.75
B8A_RX_T25N: MC2.73 MC2B.33 | length 1195.4
  Top Layer w10: v1(1113.89,2072.89) 1114.17,2073.17 MC2.73
  Bottom Layer w10: MC2B.33 511.89,2913.31 511.89,2848.11 1113.89,2246.11 v1(1113.89,2072.89)
B8A_RX_T25P: MC2.71 MC2B.31 | length 1234
  Top Layer w10: MC2.71 1145.67,2044.11 v1(1145.89,2043.89)
  Bottom Layer w10: MC2B.31 590.89,2913.05 590.89,2804.11 1145.89,2249.11 v1(1145.89,2043.89)
B8A_TX_T32N: MC2.74 MC2B.34 | length 882.9
  Top Layer w10: MC2B.34 693.46,2653 879,2653 1114.37,2417.63 MC2.74@1114.37,2365.75
B8A_TX_T32P: MC2.72 MC2B.32 | length 837.5
  Top Layer w10: MC2B.32 744.2,2681 885.78,2681 1145.87,2420.91 MC2.72@1145.87,2365.75
DGND: C1.1 J1.2 J2.2 J2.10 MC1.2 MC1.14 MC1.35 MC1.55 MC1.78 MC1.80 MC1A.2 MC1A.14 MC1A.35 MC1B.15 MC1B.38 MC1B.40 MC2.1 MC2.13 MC2.14 MC2.36 MC2.56 MC2.78 MC2.80 MC2A.1 MC2A.13 MC2A.14 MC2A.36 MC2B.16 MC2B.38 MC2B.40 TP10.1 TP11.1 TP12.1 TP13.1 | length 807.9
  Top Layer w16: C1.1 v1(511.89,1699.89) ; MC1.80 v1@1019.68,840.89 ; MC2.80@1019.88,2365.75 1019.88,2443.88 v1(1020,2444) ; v1(1050.89,2415.89) 1051.38,2415.4 MC2.78@1051.38,2365.75 ; MC1.78 v1@1051.18,868.89 ; MC1.55 1397.64,498.14 v1(1397.89,497.89) ; MC2.56@1397.83,2365.75 1397.83,2415.83 v1(1397.89,2415.89) ; MC1.35 1712.6,498.18 v1(1712.89,497.89) ; MC2.36@1712.8,2365.75 1712.8,2415.8 v1(1712.89,2415.89) ; v1(2058.89,2072.89) 2059.25,2073.25 MC2.13@2059.25,2122.83 ; v1(2058.89,2415.89) 2059.25,2415.53 MC2.14@2059.25,2365.75 ; MC1.14 2059.05,870.36 2058.89,870.53 v1@2059.25,870.89 ; v1(2247.89,868.89) 2248.03,868.75 MC1.2 ; v1(2247.89,2072.89) 2248.23,2073.23 MC2.1@2248.23,2122.83
  other v1: 1019.89,840.89 1050.89,868.89 2058.89,868.89
FPGA_TCK: J2.1 MC2.5 | length 3010
  Top Layer w10: J2.1 167.89,1566.32 167.89,1192.89 240.89,1119.89 1298.89,1119.89 2185.04,2006.04 MC2.5
FPGA_TDI: J2.9 MC2.9 | length 2354.6
  Top Layer w10: J2.9 307.58,1175.89 1270.89,1175.89 2122.05,2027.05 MC2.9
FPGA_TDO: J2.3 MC2.8 | length 2327.3
  Top Layer w10: J2.3 295.89,1594.32 295.89,1674.89 881.89,2260.89 2095.89,2260.89 2153.54,2318.54 MC2.8
FPGA_TMS: J2.5 MC2.7 | length 2709.3
  Top Layer w10: J2.5 190.89,1389.32 190.89,1205.89 249.89,1146.89 1282.89,1146.89 2153.54,2017.54 MC2.7
MC1_63: MC1.63 MC1B.23 | length 676.4
  Top Layer w10: MC1B.23 866.14,82.14 1271.65,487.65 MC1.63
MC1_64: MC1.64 MC1B.24 | length 1098.4
  Top Layer w10: v1(1270.68,840.89) 1271.65,839.91 MC1.64
  Bottom Layer w10: MC1B.24 904,-1.51 904,244 1270.68,610.68 v1(1270.68,840.89)
MC1_65: MC1.65 MC1B.25 | length 696.6
  Top Layer w10: MC1B.25 788.37,39.37 1240.16,491.16 MC1.65
MC1_66: MC1.66 MC1B.26 | length 1174.4
  Top Layer w10: MC1.66 1240.16,868.37 v1(1240.68,868.89)
  Bottom Layer w10: MC1B.26 825,-1.77 825,205 1240.68,620.68 v1(1240.68,868.89)
MC1_67: MC1.67 MC1B.27 | length 741.8
  Top Layer w10: MC1B.27 767.29,98 812,98 1208.66,494.66 MC1.67
MC1_68: MC1.68 MC1B.28 | length 1137.5
  Top Layer w10: MC1.68 v1@1208.66,840.87
  Bottom Layer w10: MC1B.28 749,0.97 749,169 1208.68,628.68 v1(1208.68,840.89)
MC1_69: MC1.69 MC1B.29 | length 787
  Top Layer w10: MC1B.29 716.55,126 805,126 1177.17,498.17 MC1.69
MC1_70: MC1.70 MC1B.30 | length 1213.5
  Top Layer w10: MC1.70 1177.17,868.38 v1(1177.68,868.89)
  Bottom Layer w10: MC1B.30 670,0.71 670,130 1177.68,637.68 v1(1177.68,868.89)
MC1_71: MC1.71 MC1B.31 | length 832.1
  Top Layer w10: MC1B.31 665.81,154 798,154 1145.67,501.67 MC1.71
MC1_72: MC1.72 MC1B.32 | length 1176.7
  Top Layer w10: MC1.72 v1(1145.68,840.89)
  Bottom Layer w10: MC1B.32 590,-0.55 590,90 1145.68,645.68 v1(1145.68,840.89)
MC1_73: MC1.73 MC1B.33 | length 877.3
  Top Layer w10: MC1B.33 615.07,182 791,182 1114.17,505.17 MC1.73
MC1_74: MC1.74 MC1B.34 | length 1252.6
  Top Layer w10: MC1.74 1114.17,868.39 v1(1114.68,868.89)
  Bottom Layer w10: MC1B.34 511,-0.81 511,51 1114.68,654.68 v1(1114.68,868.89)
MC1_75: MC1.75 MC1B.35 | length 922.5
  Top Layer w10: MC1B.35 564.33,210 784,210 1082.68,508.68 MC1.75
MC1_76: MC1.76 MC1B.36 | length 1245.1
  Top Layer w10: MC1.76 v1(1082.68,840.89)
  Bottom Layer w10: MC1B.36 433,-0.07 433,63 460,90 510,90 1082.68,662.68 v1(1082.68,840.89)
MC2_75: MC2.75 MC2B.35 | length 1306.1
  Top Layer w10: MC2.75 1082.68,2044.21 v1(1083,2043.89)
  Bottom Layer w10: MC2B.35 434,2912.46 434,2835 599,2670 655,2670 1083,2242 v1(1083,2043.89)
MC2_76: MC2.76 MC2B.36 | length 932.3
  Top Layer w10: MC2B.36 642.72,2625 879,2625 1082.68,2421.32 MC2.76
NetC1_2: C1.2 J2.4 R1.1 | length 266.1
  Top Layer w16: J2.4 395.46,1593.89 C1.2@519.89,1593.89 ; C1.2 513.86,1593.43 R1.1
VCCIO_MC1: MC1.36 MC1.56 MC1A.36 MC1B.16 TP2.1 | length 2565.2
  Top Layer w16: MC1.56 1397.64,840.64 v1(1397.89,840.89) 1397.89,881.91 1416.7,900.72 1691.11,900.72 1712.6,879.23 MC1.36
  Bottom Layer w12: MC1B.16 1220.47,0 TP2.1 1220.47,400.47 1397.89,577.89 v1(1397.89,840.89) ; v1(1712.89,840.89) 1712.89,627.11 2165.89,174.11 2165.89,-0.54 MC1A.36
VCCIO_MC2: MC2.35 MC2.55 MC2A.35 MC2B.15 TP9.1 | length 2612
  Top Layer w16: MC2.55 1397.64,2044.14 v1(1397.89,2043.89) 1432.46,2009.32 1677.74,2009.32 1712.6,2044.18 MC2.35
  Bottom Layer w10: MC2B.15 1220.47,2913.39 TP9.1 1220.47,2514.53 1397.89,2337.11 v1(1397.89,2043.89) ; v1(1712.89,2043.89) 1712.89,2357.89 2165.89,2810.89 2165.89,2913.92 MC2A.35
VCCPD_MC1: MC1.12 MC1A.12 TP4.1 | length 3381.9
  Top Layer w10: MC1.12 2090.55,840.89 v1(2090.89,840.89) ; v1(2405.89,898.89) 2552.89,898.89 2585.64,866.14 TP4.1
  Bottom Layer w10: v1(2405.89,898.89) 2108.89,898.89 2090.89,880.89 v1(2090.89,840.89) 2090.89,817.89 2276.89,631.89 2528.89,631.89 3031.89,128.89 3031.89,15.89 3047.89,-0.11 3110.35,-0.11 MC1A.12
VREF_MC1: MC1.10 MC1A.10 TP7.1 | length 1720.2
  Top Layer w10: v1(2121.89,868.89) 2122.05,868.89 MC1.10
  Bottom Layer w10: v1(2121.89,868.89) 2121.89,826.89 2291.89,656.89 2761.89,656.89 3188.89,229.89 3188.89,0.09 MC1A.10
VREF_MC2: MC2.10 MC2A.10 TP8.1 | length 1373.1
  Top Layer w12: MC2.10 2122.05,2422.05 2201.89,2501.89 2895.59,2501.89 TP8.1 3228.35,2834.64 MC2A.10
pads on no net: FID1.FID? FID2.FID? FID3.FID? FID4.FID? FID5.FID? FID6.FID? FID7.FID? FID8.FID? J1.3 J2.6 J2.7 J2.8 MC1.81 MC1.82 MC2.3 MC2.12 MC2.81 MC2.82 MC2A.3 MC2A.5 MC2A.7 MC2A.8 MC2A.9 MC2A.12

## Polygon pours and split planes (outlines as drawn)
DGND on Bottom Layer "Bottom Layer-No Net" (solid, remove dead copper, pour order 1000): -118.11,3031.5 -118.11,-118.11 4606.3,-118.11 4606.3,3031.5

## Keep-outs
Keep-Out Layer:
  the board outline again, w7.01

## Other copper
Top Layer:
  region net +5VDC: 4114.17,515.75 3972.44,515.75 3900.58,443.89 3375.89,443.89 3323.72,496.06 2177.17,496.06 2177.17,471.61 2318.07,330.71 3212.07,330.71 3346.46,196.32 3346.46,15.75 3362.21,0 3992.13,0 4177.17,185.04 4177.17,452.76

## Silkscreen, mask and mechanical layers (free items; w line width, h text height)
Top Overlay:
  lines w4.72: 629.92,2440.95 629.92,472.44 3582.68,472.44 3582.68,2440.95 635,2440.95
  text "BRK5310 / 20160317" at 4141.73,2003.94 h40 r90
  text "1:TCK" at -77.04,1622.52 h40
  text "3:TDO" at -83.7,1524.09 h40
  text "JTAG" at 488.19,1515.75 h50 r270
  text "5:TMS" at -83.7,1421.73 h40
  text "9:TDI" at -70.37,1220.94 h40
Top Solder:
  the board outline again, w1
Outline:
  the board outline again, w8
Mechanical:
  lines w10: 629.92,472.44 629.92,2440.94 3582.68,2440.94 3582.68,472.44 629.92,472.44
Fab Notes:
  drawing of 191 lines, arcs and shapes, not listed
  text "NOTES" at -513.96,6206.99 h50
  text "1. MATERIAL SELECTION:" at -513.96,6106.99 h50
  text "2-LAYER, 370HR, 0.062\" +/- 0.005 THICK" at -388.96,6031.99 h50
  text "SURFACE FINISH: ENIG (ELECTROLESS NICKEL, IMMERSION GOLD)" at -388.96,5956.99 h50
  text "2. SOLDER RESIST: GREEN LPI" at -513.96,5831.99 h50
  text "3. SILKSCREEN: WHITE / DO NOT REMOVE OVER TENTED VIAS." at -513.96,5706.99 h50
  text "4. LOT CODE IDENTIFICATION: ADD TO SILKSCREEN" at -513.96,5581.99 h50
  text "5. DRILL SIZES ARE FINISHED SIZE AFTER PLATING." at -513.96,5456.99 h50
  text "6. ELECTRICAL BARE BOARD TEST REQUIRED" at -513.96,5331.99 h50
  text "7. FABRICATE TO MEET EU ROHS DIRECTIVE" at -513.96,5206.99 h50
  text "8. PANELIZATION:" at -513.96,5086.56 h50
  text "1 PIECE PER PANEL" at -388.96,5011.56 h50
  text "0.1-IN RAILS ON ALL SIDES" at -388.96,4936.56 h50
  text "0.1-IN TAB ROUTING WITH MOUSE-BITES FOR BOARD SEPARATION" at -388.96,4861.56 h50
  text "MOUSE BITE LOCATIONS INDICATED BY :::" at -389.04,4787.02 h50
  text "Layer" at 3867.23,4472.89 h60
  text "Name" at 4277.15,4472.89 h60
  text "Material" at 5206.89,4472.89 h60
  text "Thickness" at 6066.66,4472.89 h60
  text "Constant" at 6716.49,4472.89 h60
  text "Board Layer Stack" at 7286.35,4472.89 h60
  text "1" at 3867.23,4352.89 h60
  text "Top Overlay" at 4277.15,4352.89 h60
  text "2" at 3867.23,4232.89 h60
  text "Top Solder" at 4277.15,4232.89 h60
  text "Solder Resist" at 5206.89,4232.89 h60
  text "0.40mil" at 6066.66,4232.89 h60
  text "3.5" at 6716.49,4232.89 h60
  text "3" at 3867.23,4112.89 h60
  text "Top Layer" at 4277.15,4112.89 h60
  text "Copper" at 5206.89,4112.89 h60
  text "1.40mil" at 6066.66,4112.89 h60
  text "4" at 3867.23,3992.89 h60
  text "Dielectric1" at 4277.15,3992.89 h60
  text "FR-4" at 5206.89,3992.89 h60
  text "62.00mil" at 6066.66,3992.89 h60
  text "4.8" at 6716.49,3992.89 h60
  text "5" at 3867.23,3872.89 h60
  text "Bottom Layer" at 4277.15,3872.89 h60
  text "Copper" at 5206.89,3872.89 h60
  text "1.40mil" at 6066.66,3872.89 h60
  text "6" at 3867.23,3752.89 h60
  text "Bottom Solder" at 4277.15,3752.89 h60
  text "Solder Resist" at 5206.89,3752.89 h60
  text "0.40mil" at 6066.66,3752.89 h60
  text "3.5" at 6716.49,3752.89 h60
  text "7" at 3867.23,3632.89 h60
  text "Bottom Overlay" at 4277.15,3632.89 h60
  text ":::" at 1860.89,3066.89 h50
  text ":::" at -155.11,1419.89 h50 r90
  text ":::" at 4672.89,1414.89 h50 r90
  text ":::" at 1833.89,-182.11 h50
Drill Drawing:
  circle w10: c3496.92,5537.67 r27.78
  lines w10: 3469.14,5134.89 3496.92,5148.78 3524.7,5134.89 3510.81,5162.67 3524.7,5190.45 3496.92,5176.56 3469.14,5190.45 3483.03,5162.67 3469.14,5134.89 ; 3469.14,5315.45 3524.7,5315.45 3496.92,5259.89 3469.14,5315.45 ; 3469.14,5384.89 3524.7,5384.89 3524.7,5440.45 3469.14,5440.45 3469.14,5384.89 ; 3469.14,5648.78 3483.03,5648.78 3496.92,5634.89 3510.81,5648.78 3524.7,5648.78 3510.81,5662.67 3524.7,5676.56 3510.81,5676.56 3496.92,5690.45 3483.03,5676.56 3469.14,5676.56 3483.03,5662.67 3469.14,5648.78 ; 3469.14,5773.78 3483.03,5773.78 3483.03,5759.89 3510.81,5759.89 3510.81,5773.78 3524.7,5773.78 3524.7,5801.56 3510.81,5801.56 3510.81,5815.45 3483.03,5815.45 3483.03,5801.56 3469.14,5801.56 3469.14,5773.78 ; 3469.14,5884.89 3469.14,5898.78 3483.03,5912.67 3469.14,5926.56 3469.14,5940.45 3483.03,5940.45 3496.92,5926.56 3510.81,5940.45 3524.7,5940.45 3524.7,5926.56 3510.81,5912.67 3524.7,5898.78 3524.7,5884.89 3510.81,5884.89 3496.92,5898.78 3483.03,5884.89 3469.14,5884.89
  lines w15: 3418.79,5097.39 8814,5097.39 ; 3418.79,5972.39 8814,5972.39 ; 3883.19,4972.39 3883.19,6097.39 ; 4386.39,4972.39 4386.39,6097.39 ; 5306.12,4972.39 5306.12,6097.39 ; 5733.02,4972.39 5733.02,6097.39 ; 6349.85,4972.39 6349.85,6097.39 ; 7602.81,4972.39 7602.81,6097.39 ; 8099.69,4972.39 8099.69,6097.39 ; 3418.79,4972.39 8814,4972.39 8814,6097.39 3418.79,6097.39 3418.79,4972.39
  text "Symbol" at 3493.79,6009.89 h60
  text "Count" at 3920.69,6009.89 h60
  text "Hole Size" at 4423.89,6009.89 h60
  text "Plated" at 5343.62,6009.89 h60
  text "Hole Type" at 5770.52,6009.89 h60
  text "Drill Layer Pair" at 6387.35,6009.89 h60
  text "Via/Pad" at 7640.31,6009.89 h60
  text "Technology" at 8137.19,6009.89 h60
  text "84" at 3920.69,5884.89 h50
  text "10.00mil (0.254mm)" at 4423.89,5884.89 h50
  text "PTH" at 5343.62,5884.89 h50
  text "Round" at 5770.52,5884.89 h50
  text "Top Layer - Bottom Layer" at 6387.35,5884.89 h50
  text "Via" at 7640.31,5884.89 h50
  text "Drilled" at 8137.19,5884.89 h50
  text "160" at 3920.69,5759.89 h50
  text "31.50mil (0.800mm)" at 4423.89,5759.89 h50
  text "PTH" at 5343.62,5759.89 h50
  text "Round" at 5770.52,5759.89 h50
  text "Top Layer - Bottom Layer" at 6387.35,5759.89 h50
  text "Pad" at 7640.31,5759.89 h50
  text "Drilled" at 8137.19,5759.89 h50
  text "4" at 3920.69,5634.89 h50
  text "40.16mil (1.020mm)" at 4423.89,5634.89 h50
  text "PTH" at 5343.62,5634.89 h50
  text "Round" at 5770.52,5634.89 h50
  text "Top Layer - Bottom Layer" at 6387.35,5634.89 h50
  text "Pad" at 7640.31,5634.89 h50
  text "Drilled" at 8137.19,5634.89 h50
  text "10" at 3920.69,5509.89 h50
  text "44.88mil (1.140mm)" at 4423.89,5509.89 h50
  text "PTH" at 5343.62,5509.89 h50
  text "Round" at 5770.52,5509.89 h50
  text "Top Layer - Bottom Layer" at 6387.35,5509.89 h50
  text "Pad" at 7640.31,5509.89 h50
  text "Drilled" at 8137.19,5509.89 h50
  text "3" at 3920.69,5384.89 h50
  text "59.06mil (1.500mm)" at 4423.89,5384.89 h50
  text "PTH" at 5343.62,5384.89 h50
  text "Round" at 5770.52,5384.89 h50
  text "Top Layer - Bottom Layer" at 6387.35,5384.89 h50
  text "Pad" at 7640.31,5384.89 h50
  text "Drilled" at 8137.19,5384.89 h50
  text "13" at 3920.69,5259.89 h50
  text "65.00mil (1.651mm)" at 4423.89,5259.89 h50
  text "PTH" at 5343.62,5259.89 h50
  text "Round" at 5770.52,5259.89 h50
  text "Top Layer - Bottom Layer" at 6387.35,5259.89 h50
  text "Pad" at 7640.31,5259.89 h50
  text "Drilled" at 8137.19,5259.89 h50
  text "8" at 3920.69,5134.89 h50
  text "98.43mil (2.500mm)" at 4423.89,5134.89 h50
  text "PTH" at 5343.62,5134.89 h50
  text "Round" at 5770.52,5134.89 h50
  text "Top Layer - Bottom Layer" at 6387.35,5134.89 h50
  text "Pad" at 7640.31,5134.89 h50
  text "Drilled" at 8137.19,5134.89 h50
  text "282 Total" at 3920.69,5009.89 h50
Doc-Assy-Top:
  lines w2.94: -927.76,-91.93 -810,-91.93 ; -927.76,1159.24 -810,1159.24 ; -927.76,2410.4 -810,2410.4 ; 573.64,-1225.34 573.64,-1107.58 ; 573.64,3426.06 573.64,3543.81 ; 2192.8,-1225.34 2192.8,-1107.58 ; 2192.8,3426.06 2192.8,3543.81 ; 2663.83,-1225.34 5313.36,-1225.34 ; 3431.11,-1107.58 3431.11,-756.17 ; 3431.11,-967.57 5195.6,-967.57 ; 3811.96,-1225.34 3811.96,-1107.58 ; 3811.96,3426.06 3811.96,3543.81 ; 4193.11,-825.71 4193.11,-547.72 ; 4647.45,-967.57 4647.45,-825.89 ; 5195.6,-825.89 3431.11,-825.89 3431.11,-547.72 5195.6,-547.72 ; 5195.6,-91.93 5313.36,-91.93 ; 5195.6,1159.24 5313.36,1159.24 ; 5195.6,2410.4 5313.36,2410.4 ; 5313.36,-1225.34 -927.76,-1225.34 -927.76,3543.81 5313.36,3543.81 5313.36,-1225.34 ; -810,-1107.58 5195.6,-1107.58 5195.6,3426.06 -810,3426.06 -810,-1107.58
  text "1" at -249.87,3466.18 h41.21
  text "2" at 1369.68,3466.18 h41.21
  text "3" at 2985.9,3466.18 h41.21
  text "4" at 4605.65,3466.18 h41.21
  text "A" at -885.45,2982.7 h41.21
  text "A" at 5241.62,2982.7 h41.21
  text "B" at -885.45,1731.54 h41.21
  text "B" at 5241.62,1731.54 h41.21
  text "C" at -885.45,480.37 h41.21
  text "C" at 5241.62,480.37 h41.21
  text "TITLE:" at 3476.83,-594.08 h26.5
  text "Opal Kelly" at 4239.47,-612.63 h41.21
  text "13500 SW 72nd Ave Suite 100" at 4239.47,-682.17 h41.21
  text "Portland, OR 97223" at 4239.47,-740.12 h41.21
  text "BRK5310 / Assembly Drawing" at 3495.89,-741.11 h41.21
  text "D" at -885.45,-767.86 h41.21
  text "D" at 5241.62,-767.86 h41.21
  text "www.opalkelly.com" at 4239.47,-798.07 h41.21
  text "(Top)" at 3495.89,-808.23 h41.21
  text "DATE:" at 3476.83,-872.25 h26.5
  text "TIME:" at 3956.61,-873 h26.5
  text "SIZE:" at 4703.08,-873 h26.5
  text ".PRINT_DATE" at 3499.26,-943.65 h41.21
  text ".Print_Time" at 3986.05,-943.65 h41.21
  text "ANSI A" at 4730.9,-943.65 h41.21
  text "FILE NAME:" at 3476.83,-1011.33 h26.5
  text ".PCB_FILE_NAME" at 3500.01,-1080.87 h41.21
  text "1" at -249.87,-1188.93 h41.21
  text "2" at 1369.68,-1188.93 h41.21
  text "3" at 2985.9,-1188.93 h41.21
  text "4" at 4605.65,-1188.93 h41.21
Doc-Assy-Bot:
  lines w2.94: -927.11,-92.71 -809.36,-92.71 ; -927.11,1158.45 -809.36,1158.45 ; -927.11,2409.61 -809.36,2409.61 ; -809.36,-968.35 955.13,-968.35 ; -809.36,-826.66 955.13,-826.66 955.13,-548.49 -809.36,-548.49 ; -261.2,-968.35 -261.2,-826.66 ; 193.13,-826.48 193.13,-548.49 ; 574.28,-1226.11 574.28,-1108.35 ; 574.28,3425.26 574.28,3543.01 ; 955.13,-1108.35 955.13,-756.94 ; 1722.4,-1226.11 -927.11,-1226.11 ; 2193.43,-1226.11 2193.43,-1108.35 ; 2193.43,3425.26 2193.43,3543.01 ; 3812.57,-1226.11 3812.57,-1108.35 ; 3812.57,3425.26 3812.57,3543.01 ; 5196.21,-92.71 5313.96,-92.71 ; 5196.21,1158.45 5313.96,1158.45 ; 5196.21,2409.61 5313.96,2409.61 ; -927.11,-1226.11 5313.96,-1226.11 5313.96,3543.01 -927.11,3543.01 -927.11,-1226.11 ; -809.36,-1108.35 5196.21,-1108.35 5196.21,3425.26 -809.36,3425.26 -809.36,-1108.35
  text "4" at -219.4,3465.38 h41.21
  text "3" at 1400.34,3465.38 h41.21
  text "2" at 3016.54,3465.38 h41.21
  text "1" at 4636.08,3465.38 h41.21
  text "A" at -855.37,2981.9 h41.21
  text "A" at 5271.66,2981.9 h41.21
  text "B" at -855.37,1730.75 h41.21
  text "B" at 5271.66,1730.75 h41.21
  text "C" at -855.37,479.59 h41.21
  text "C" at 5271.66,479.59 h41.21
  text "TITLE:" at 909.41,-594.85 h26.5
  text "Opal Kelly" at 146.77,-613.4 h41.21
  text "13500 SW 72nd Ave Suite 100" at 146.77,-682.94 h41.21
  text "Portland, OR 97223" at 146.77,-740.89 h41.21
  text "BRK5310 / Assembly Drawing" at 890.35,-741.88 h41.21
  text "D" at -855.37,-768.63 h41.21
  text "D" at 5271.66,-768.63 h41.21
  text "www.opalkelly.com" at 146.77,-798.84 h41.21
  text "(Bottom)" at 890.35,-809 h41.21
  text "DATE:" at 909.41,-873.02 h26.5
  text "SIZE:" at -316.83,-873.77 h26.5
  text "TIME:" at 429.63,-873.77 h26.5
  text "ANSI A" at -344.65,-944.42 h41.21
  text ".Print_Time" at 400.2,-944.42 h41.21
  text ".PRINT_DATE" at 886.98,-944.42 h41.21
  text "FILE NAME:" at 909.41,-1012.1 h26.5
  text ".PCB_FILE_NAME" at 886.23,-1081.64 h41.21
  text "4" at -219.4,-1189.69 h41.21
  text "3" at 1400.34,-1189.69 h41.21
  text "2" at 3016.54,-1189.69 h41.21
  text "1" at 4636.08,-1189.69 h41.21
Doc-Fab:
  lines w5: -1111.46,628.15 -911.46,628.15 ; -1111.46,2753.15 -911.46,2753.15 ; -1111.46,4878.15 -911.46,4878.15 ; 1438.54,-1296.85 1438.54,-1096.85 ; 1438.54,6603.15 1438.54,6803.15 ; 4188.54,-1296.85 4188.54,-1096.85 ; 4188.54,6603.15 4188.54,6803.15 ; 4988.54,-1296.85 9488.54,-1296.85 ; 6291.69,-1096.85 6291.69,-500 ; 6291.69,-859.06 9288.54,-859.06 ; 6938.54,-1296.85 6938.54,-1096.85 ; 6938.54,6603.15 6938.54,6803.15 ; 7585.89,-618.11 7585.89,-145.97 ; 8357.54,-859.06 8357.54,-618.41 ; 9288.54,-618.41 6291.69,-618.41 6291.69,-145.97 9288.54,-145.97 ; 9288.54,628.15 9488.54,628.15 ; 9288.54,2753.15 9488.54,2753.15 ; 9288.54,4878.15 9488.54,4878.15 ; 9488.54,-1296.85 9488.54,6803.15 -1111.46,6803.15 -1111.46,-1296.85 9488.54,-1296.85 ; -911.46,-1096.85 -911.46,6603.15 9288.54,6603.15 9288.54,-1096.85 -911.46,-1096.85
  text "1" at 39.88,6671.3 h70
  text "2" at 2790.54,6671.3 h70
  text "3" at 5535.54,6671.3 h70
  text "4" at 8286.55,6671.3 h70
  text "A" at -1039.61,5850.15 h70
  text "A" at 9366.69,5850.15 h70
  text "B" at -1039.61,3725.15 h70
  text "B" at 9366.69,3725.15 h70
  text "C" at -1039.61,1600.15 h70
  text "C" at 9366.69,1600.15 h70
  text "TITLE:" at 6369.35,-224.71 h45
  text "Opal Kelly" at 7664.63,-256.2 h70
  text "13500 SW 72nd Ave Suite 100" at 7664.63,-374.31 h70
  text "Portland, OR 97223" at 7664.63,-472.74 h70
  text "BRK5310 / Fabrication Drawing" at 6400.44,-500.3 h70
  text "D" at -1039.61,-519.85 h70
  text "D" at 9366.69,-519.85 h70
  text "www.opalkelly.com" at 7664.63,-571.17 h70
  text "DATE:" at 6369.35,-697.15 h45
  text "TIME:" at 7184.21,-698.43 h45
  text "SIZE:" at 8452.03,-698.43 h45
  text ".PRINT_DATE" at 6407.44,-818.43 h70
  text ".Print_Time" at 7234.21,-818.43 h70
  text "ANSI A" at 8499.28,-818.43 h70
  text "FILE NAME:" at 6369.35,-933.37 h45
  text ".PCB_FILE_NAME" at 6408.72,-1051.48 h70
  text "1" at 39.88,-1235 h70
  text "2" at 2790.54,-1235 h70
  text "3" at 5535.54,-1235 h70
  text "4" at 8286.55,-1235 h70

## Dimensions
0,2913.39 to 0,0 on Dimensions
-118.11,-118.11 to -118.11,3031.5 on Dimensions
0,0 to 4488.19,0 on Dimensions
-118.11,-118.11 to 4606.3,-118.11 on Dimensions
